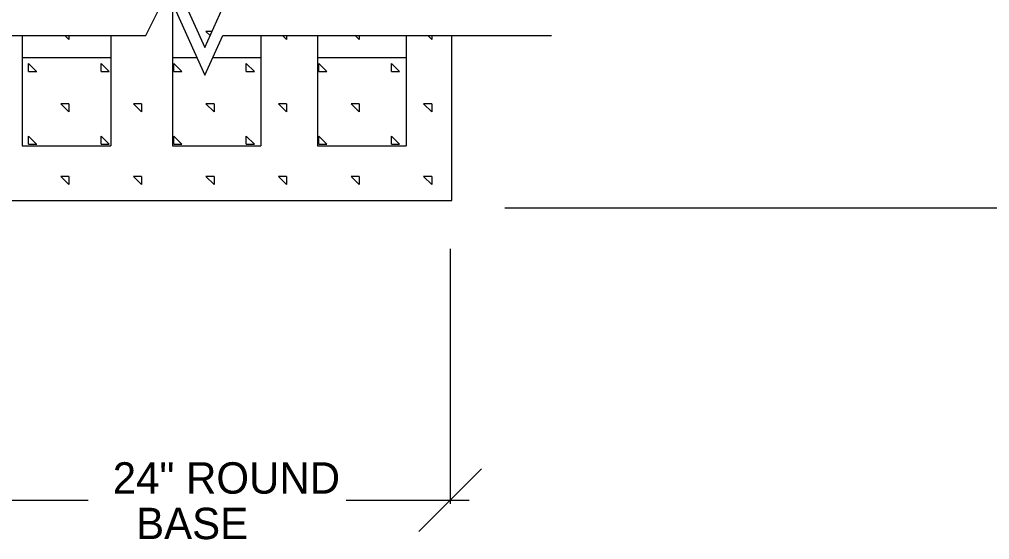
# Model space of a CAD drawing. Extents: x 10112 to 10168, y 10050 to 10179.
# Drawn here: x 10136.31 to 10156.9, y 10073.13 to 10084.18 of the extents above; entities that cross this region are included whole.
import ezdxf

# ---------------------------------------------------------------- set-up
doc = ezdxf.new("R2010")
doc.units = 0
for name, color, linetype in [('G-ANNO-TEXT', 7, 'Continuous'), ('G-DETL-LINE', 7, 'Continuous'), ('G-DETL-OTLN', 7, 'Continuous'), ('G-DETL-PATT', 7, 'Continuous')]:
    doc.layers.add(name, color=color, linetype=linetype)

msp = doc.modelspace()

# ---------------------------------------------------------------- linework, layer by layer
at = {"layer": 'G-ANNO-TEXT'}
for p, q in [((10146.605, 10080.178), (10167.775, 10080.178)), ((10145.446, 10079.307), (10145.446, 10073.89)), ((10144.781, 10073.306), (10146.111, 10074.636)), ((10135.106, 10073.971), (10137.767, 10073.971)), ((10143.243, 10073.971), (10145.85, 10073.971))]:
    msp.add_line(p, q, dxfattribs=at)
at = {"layer": 'G-DETL-LINE'}
for p, q in [((10139.553, 10084.522), (10139.553, 10081.489)), ((10136.367, 10083.838), (10136.367, 10081.489)), ((10138.245, 10083.838), (10138.245, 10081.489)), ((10141.43, 10083.838), (10141.43, 10081.489)), ((10142.634, 10083.838), (10142.634, 10081.489)), ((10144.511, 10083.838), (10144.511, 10081.489)), ((10136.367, 10083.367), (10138.245, 10083.367)), ((10139.553, 10083.367), (10140.07, 10083.367)), ((10140.409, 10083.367), (10141.43, 10083.367)), ((10142.634, 10083.367), (10144.511, 10083.367)), ((10136.367, 10081.489), (10138.245, 10081.489)), ((10139.553, 10081.489), (10141.43, 10081.489)), ((10142.634, 10081.489), (10144.511, 10081.489))]:
    msp.add_line(p, q, dxfattribs=at)
at = {"layer": 'G-DETL-OTLN'}
for p, q in [((10145.484, 10080.33), (10145.484, 10083.838)), ((10135.445, 10080.33), (10145.484, 10080.33))]:
    msp.add_line(p, q, dxfattribs=at)
at = {"layer": 'G-DETL-PATT'}
for p, q in [((10139.447, 10085.348), (10140.24, 10083.58)), ((10138.985, 10083.838), (10139.447, 10084.757)), ((10139.447, 10084.757), (10140.24, 10082.989)), ((10140.24, 10083.58), (10140.62, 10084.43)), ((10132.608, 10083.838), (10138.985, 10083.838)), ((10137.356, 10083.752), (10137.27, 10083.838)), ((10137.356, 10083.838), (10137.356, 10083.752)), ((10140.24, 10082.989), (10140.62, 10083.838)), ((10140.393, 10083.923), (10140.265, 10083.923)), ((10140.354, 10083.835), (10140.265, 10083.923)), ((10140.62, 10083.838), (10147.596, 10083.838)), ((10141.976, 10083.752), (10141.89, 10083.838)), ((10141.976, 10083.838), (10141.976, 10083.752)), ((10143.516, 10083.752), (10143.43, 10083.838)), ((10143.516, 10083.838), (10143.516, 10083.752)), ((10145.056, 10083.752), (10144.97, 10083.838)), ((10145.056, 10083.838), (10145.056, 10083.752)), ((10140.564, 10083.67), (10140.564, 10083.67)), ((10136.5, 10083.068), (10136.5, 10083.239)), ((10136.671, 10083.068), (10136.5, 10083.239)), ((10138.04, 10083.068), (10138.04, 10083.239)), ((10138.212, 10083.068), (10138.04, 10083.239)), ((10139.58, 10083.068), (10139.58, 10083.239)), ((10139.752, 10083.068), (10139.58, 10083.239)), ((10141.121, 10083.068), (10141.121, 10083.239)), ((10141.292, 10083.068), (10141.121, 10083.239)), ((10142.661, 10083.068), (10142.661, 10083.239)), ((10142.832, 10083.068), (10142.661, 10083.239)), ((10144.201, 10083.068), (10144.201, 10083.239)), ((10144.372, 10083.068), (10144.201, 10083.239)), ((10136.5, 10083.068), (10136.672, 10083.068)), ((10138.04, 10083.068), (10138.212, 10083.068)), ((10139.58, 10083.068), (10139.752, 10083.068)), ((10141.121, 10083.068), (10141.292, 10083.068)), ((10142.661, 10083.068), (10142.832, 10083.068)), ((10144.201, 10083.068), (10144.372, 10083.068)), ((10137.356, 10082.383), (10137.185, 10082.383)), ((10137.356, 10082.212), (10137.185, 10082.383)), ((10137.356, 10082.383), (10137.356, 10082.212)), ((10138.896, 10082.383), (10138.725, 10082.383)), ((10138.896, 10082.212), (10138.725, 10082.383)), ((10138.896, 10082.383), (10138.896, 10082.212)), ((10140.436, 10082.383), (10140.265, 10082.383)), ((10140.436, 10082.212), (10140.265, 10082.383)), ((10140.436, 10082.383), (10140.436, 10082.212)), ((10141.976, 10082.383), (10141.805, 10082.383)), ((10141.976, 10082.212), (10141.805, 10082.383)), ((10141.976, 10082.383), (10141.976, 10082.212)), ((10143.516, 10082.383), (10143.345, 10082.383)), ((10143.516, 10082.212), (10143.345, 10082.383)), ((10143.516, 10082.383), (10143.516, 10082.212)), ((10145.056, 10082.383), (10144.885, 10082.383)), ((10145.056, 10082.212), (10144.885, 10082.383)), ((10145.056, 10082.383), (10145.056, 10082.212)), ((10136.5, 10081.528), (10136.5, 10081.699)), ((10136.671, 10081.528), (10136.5, 10081.699)), ((10136.5, 10081.528), (10136.672, 10081.528)), ((10138.04, 10081.528), (10138.04, 10081.699)), ((10138.212, 10081.528), (10138.04, 10081.699)), ((10138.04, 10081.528), (10138.212, 10081.528)), ((10139.58, 10081.528), (10139.58, 10081.699)), ((10139.752, 10081.528), (10139.58, 10081.699)), ((10139.58, 10081.528), (10139.752, 10081.528)), ((10141.121, 10081.528), (10141.121, 10081.699)), ((10141.292, 10081.528), (10141.121, 10081.699)), ((10141.121, 10081.528), (10141.292, 10081.528)), ((10141.223, 10081.605), (10141.223, 10081.605)), ((10142.661, 10081.528), (10142.661, 10081.699)), ((10142.832, 10081.528), (10142.661, 10081.699)), ((10142.661, 10081.528), (10142.832, 10081.528)), ((10144.201, 10081.528), (10144.201, 10081.699)), ((10144.372, 10081.528), (10144.201, 10081.699)), ((10144.201, 10081.528), (10144.372, 10081.528)), ((10137.356, 10080.843), (10137.185, 10080.843)), ((10137.356, 10080.672), (10137.185, 10080.843)), ((10137.356, 10080.843), (10137.356, 10080.672)), ((10137.386, 10080.847), (10137.386, 10080.847)), ((10138.896, 10080.843), (10138.725, 10080.843)), ((10138.896, 10080.672), (10138.725, 10080.843)), ((10138.896, 10080.843), (10138.896, 10080.672)), ((10140.436, 10080.843), (10140.265, 10080.843)), ((10140.436, 10080.672), (10140.265, 10080.843)), ((10140.436, 10080.843), (10140.436, 10080.672)), ((10141.976, 10080.843), (10141.805, 10080.843)), ((10141.976, 10080.672), (10141.805, 10080.843)), ((10141.976, 10080.843), (10141.976, 10080.672)), ((10143.516, 10080.843), (10143.345, 10080.843)), ((10143.516, 10080.672), (10143.345, 10080.843)), ((10143.516, 10080.843), (10143.516, 10080.672)), ((10145.056, 10080.843), (10144.885, 10080.843)), ((10145.056, 10080.672), (10144.885, 10080.843)), ((10145.056, 10080.843), (10145.056, 10080.672))]:
    msp.add_line(p, q, dxfattribs=at)

# ---------------------------------------------------------------- texts
at = {"layer": 'G-ANNO-TEXT'}
for s, p in [('24" ROUND', (10138.286, 10074.107)), ('  BASE', (10138.286, 10073.141))]:
    msp.add_text(s, height=0.6667, dxfattribs=at).set_placement(p)

doc.saveas('drawing.dxf')
